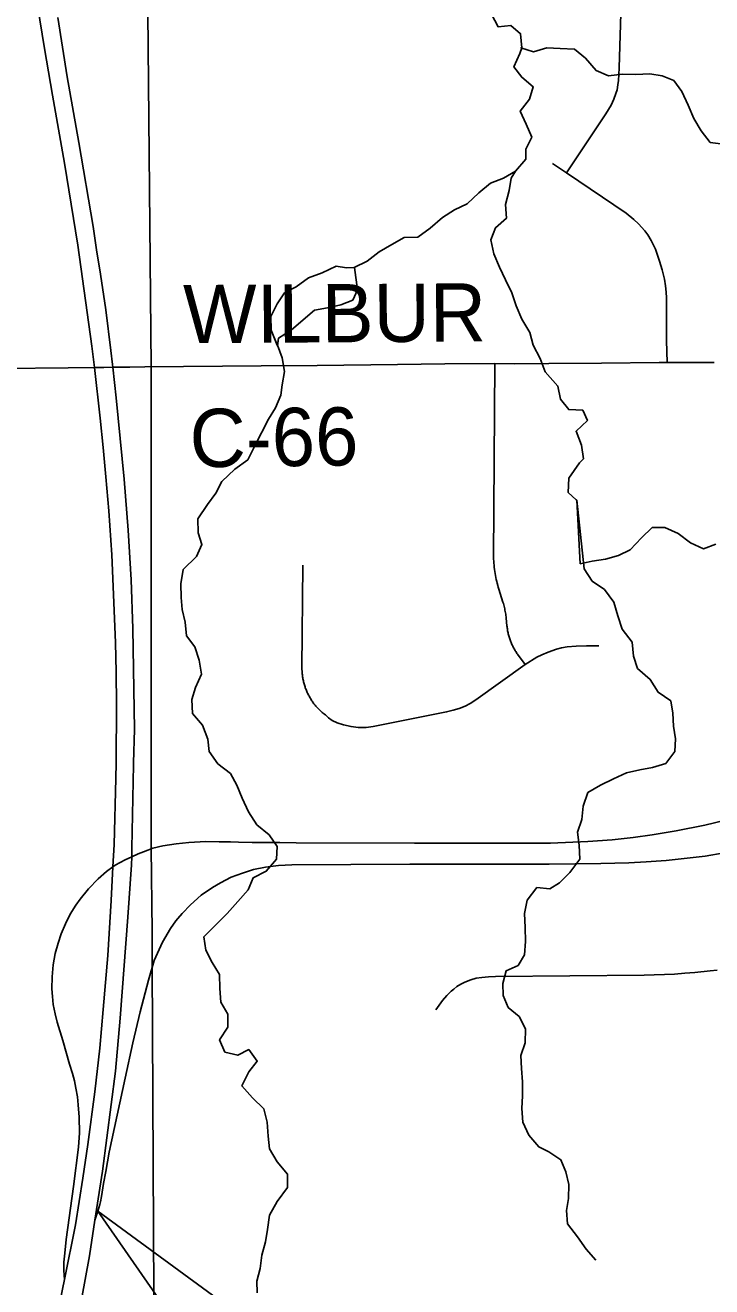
# Model space of a CAD drawing. Extents: x 0 to 34, y 0 to 22.
# Drawn here: x 2.725 to 3.395, y 15.885 to 17.117 of the extents above; entities that cross this region are included whole.
import ezdxf

# ---------------------------------------------------------------- set-up
doc = ezdxf.new("R2010")
doc.units = 0
for name, color, linetype in [('GM_X_Corporation', 7, 'Continuous'), ('GM_X_County_Road', 7, 'Continuous'), ('GM_X_County_Road_Text', 7, 'Continuous'), ('GM_X_Interstate_Route', 7, 'Continuous'), ('GM_X_Minor_Lake', 7, 'Continuous'), ('GM_X_Minor_River', 7, 'Continuous'), ('GM_X_Township_Road', 7, 'Continuous'), ('SH_Text', 7, 'Continuous')]:
    doc.layers.add(name, color=color, linetype=linetype)

msp = doc.modelspace()

# ---------------------------------------------------------------- linework, layer by layer
at = {"layer": 'GM_X_Corporation'}
msp.add_lwpolyline([(2.1, 19.0167), (2.1, 14.5179), (2.2213, 14.5194), (2.2958, 14.5199), (2.3573, 14.5203), (2.3767, 14.5206), (2.4262, 14.5205), (2.6122, 14.5212), (2.8483, 14.5213), (2.8655, 14.5214), (2.8502, 15.8768), (2.8488, 16.2), (2.8487, 16.2273), (2.8487, 16.232), (2.8477, 16.3135), (2.8476, 16.3157), (2.8477, 16.7834), (2.837, 17.9259), (2.8293, 18.7154), (2.8247, 19.0323), (2.4392, 19.024), (2.4288, 19.0238), (2.421, 19.0236)], close=True, dxfattribs=at)
msp.add_lwpolyline([(3.735, 14.5275), (3.3839, 14.5264), (3.3511, 14.525), (2.8655, 14.5214), (2.8502, 15.8768), (2.8488, 16.2), (2.8487, 16.2273), (2.8487, 16.232), (2.8477, 16.3135), (2.8476, 16.3157), (2.8477, 16.7834), (2.837, 17.9259), (2.8293, 18.7154)], dxfattribs=at)
at = {"layer": 'GM_X_County_Road'}
for points in [[(2.8415, 16.7834), (2.9551, 16.7841), (3.0098, 16.7846), (3.0879, 16.7857), (3.1342, 16.7862), (3.1831, 16.7864), (3.2019, 16.7863), (3.2356, 16.7864), (3.287, 16.7868), (3.3433, 16.7874), (3.351, 16.7874), (3.397, 16.7875)], [(2.6084, 16.7813), (2.6295, 16.781), (2.6551, 16.7811), (2.7026, 16.7818), (2.7666, 16.7822), (2.7924, 16.7825), (2.8017, 16.7826), (2.8104, 16.7828), (2.827, 16.7831), (2.8415, 16.7834)]]:
    msp.add_lwpolyline(points, dxfattribs=at)
at = {"layer": 'GM_X_Interstate_Route'}
msp.add_line((2.8403, 16.3099), (2.8446, 16.3115), dxfattribs=at)
for points in [[(2.8132, 16.3815), (2.8136, 16.3967), (2.814, 16.4537), (2.8136, 16.4853), (2.8129, 16.5142), (2.8093, 16.5997), (2.8065, 16.6426), (2.8036, 16.676), (2.8008, 16.7045), (2.798, 16.7331), (2.7924, 16.7825), (2.7899, 16.8036), (2.7762, 16.9019), (2.7631, 16.9822), (2.7516, 17.0485), (2.7437, 17.0939), (2.732, 17.1664)], [(2.8306, 16.3967), (2.8313, 16.4294), (2.8297, 16.528), (2.8281, 16.5753), (2.8252, 16.6239), (2.8213, 16.6735), (2.8137, 16.7531), (2.8104, 16.7828), (2.8101, 16.7857), (2.8085, 16.7991), (2.8036, 16.8389), (2.7984, 16.8736), (2.7945, 16.8976), (2.791, 16.9202), (2.777, 17.0024), (2.7659, 17.0664), (2.7566, 17.1244)], [(2.7769, 15.8595), (2.7791, 15.8703), (2.7796, 15.873), (2.7874, 15.9156), (2.7929, 15.9503), (2.8004, 15.9982), (2.8129, 16.0958), (2.8175, 16.1475), (2.8248, 16.2462), (2.8285, 16.2973), (2.8288, 16.3051), (2.829, 16.3133), (2.8306, 16.3947), (2.8306, 16.3967)], [(2.759, 15.872), (2.7631, 15.8925), (2.7738, 15.9459), (2.781, 15.9912), (2.786, 16.0242), (2.7927, 16.0757), (2.7975, 16.1183), (2.801, 16.156), (2.8053, 16.2087), (2.8087, 16.2624), (2.8104, 16.2954), (2.8115, 16.3171), (2.8132, 16.3815)], [(2.8446, 16.3115), (2.8493, 16.3133), (2.8592, 16.3158), (2.872, 16.3178), (2.8845, 16.3191), (2.901, 16.3199), (2.9142, 16.3197), (2.9251, 16.3195), (2.933, 16.3193), (2.9461, 16.3191), (2.9731, 16.3189), (2.9892, 16.3187), (3.1046, 16.3185), (3.2373, 16.3183), (3.2736, 16.3199), (3.2975, 16.3216), (3.3179, 16.3238), (3.3365, 16.3265), (3.36, 16.3304), (3.3878, 16.3358), (3.408, 16.3407)], [(2.7631, 15.8925), (2.7628, 15.8964), (2.7624, 15.9016), (2.7626, 15.9092), (2.7634, 15.9183), (2.7648, 15.9316), (2.7721, 15.9832), (2.7769, 16.0215), (2.7778, 16.0357), (2.7774, 16.0508), (2.7765, 16.0629), (2.7757, 16.0707), (2.7743, 16.0792), (2.7728, 16.0862), (2.771, 16.0934), (2.7682, 16.1026), (2.7614, 16.1258), (2.7561, 16.1437), (2.7541, 16.1517), (2.7522, 16.1608), (2.7515, 16.1686), (2.7508, 16.1763), (2.7512, 16.1878), (2.752, 16.1995), (2.7539, 16.2107), (2.757, 16.2208), (2.76, 16.23), (2.764, 16.2397), (2.7687, 16.2492), (2.7743, 16.2578), (2.7786, 16.2638), (2.7866, 16.2739), (2.7961, 16.2836), (2.8042, 16.2908), (2.8104, 16.2954), (2.8126, 16.297), (2.8223, 16.3021), (2.8288, 16.3051), (2.8351, 16.3079), (2.8403, 16.3099)], [(2.8737, 16.2447), (2.8779, 16.2497), (2.8861, 16.258), (2.8966, 16.2675), (2.9076, 16.275), (2.9153, 16.2797), (2.9258, 16.285), (2.9368, 16.2892), (2.9476, 16.2925), (2.9593, 16.295), (2.9721, 16.2965), (2.985, 16.2972), (3.1002, 16.298), (3.2361, 16.2977), (3.2864, 16.2984), (3.3136, 16.299), (3.3306, 16.3), (3.3501, 16.3015), (3.3881, 16.3057), (3.4068, 16.3089)], [(2.845, 16.1845), (2.8506, 16.2038), (2.8589, 16.2217), (2.8666, 16.235), (2.8719, 16.2425), (2.8737, 16.2447)], [(2.7929, 15.9503), (2.7956, 15.9593), (2.7965, 15.9624), (2.7975, 15.9657), (2.7982, 15.9683), (2.7992, 15.9736), (2.8013, 15.9861), (2.8034, 15.9977), (2.8069, 16.0167), (2.8225, 16.0891), (2.8299, 16.1236), (2.8371, 16.1538), (2.845, 16.1845)]]:
    msp.add_lwpolyline(points, dxfattribs=at)
at = {"layer": 'GM_X_Minor_Lake'}
for points in [[(3.046, 16.8802), (3.0382, 16.88), (3.0283, 16.8814), (3.0144, 16.8751), (3.0013, 16.8703), (2.9893, 16.8613), (2.9777, 16.8554), (2.9707, 16.8447), (2.9645, 16.8324), (2.9647, 16.8192), (2.9709, 16.8037)], [(3.0457, 16.8802), (3.0382, 16.88), (3.0283, 16.8814), (3.0144, 16.8751), (3.0013, 16.8703), (2.9893, 16.8613), (2.9777, 16.8554), (2.9707, 16.8447), (2.9645, 16.8324), (2.9647, 16.8192), (2.9706, 16.8044)], [(2.9709, 16.8037), (2.972, 16.8113), (2.9844, 16.8191), (2.9959, 16.8292), (3.0071, 16.8385), (3.0199, 16.841), (3.0328, 16.8439), (3.0444, 16.8483), (3.0491, 16.8586), (3.046, 16.8802)], [(2.971, 16.8045), (2.972, 16.8113), (2.9844, 16.8191), (2.9959, 16.8292), (3.0071, 16.8385), (3.0199, 16.841), (3.0328, 16.8439), (3.0444, 16.8483), (3.0491, 16.8586), (3.046, 16.8802)]]:
    msp.add_lwpolyline(points, dxfattribs=at)
at = {"layer": 'GM_X_Minor_River'}
for points in [[(3.1798, 17.1276), (3.1861, 17.1152), (3.1986, 17.1166), (3.2082, 17.1084), (3.2095, 17.0948)], [(3.2095, 17.0948), (3.2074, 17.089), (3.2015, 17.076), (3.2093, 17.0659), (3.2204, 17.0566), (3.2168, 17.0444), (3.2076, 17.0329), (3.2135, 17.0201), (3.219, 17.0073), (3.2132, 16.9958), (3.2133, 16.9859), (3.2033, 16.9744), (3.1913, 16.9673), (3.1789, 16.9626), (3.1674, 16.9532), (3.1559, 16.9424), (3.1435, 16.9365), (3.1319, 16.9291), (3.12, 16.9186), (3.108, 16.9097), (3.0944, 16.9095), (3.0824, 16.9028), (3.0701, 16.8954), (3.0585, 16.8864), (3.0457, 16.8802)], [(3.2095, 17.0948), (3.2084, 17.0947), (3.2206, 17.0908), (3.2337, 17.0948), (3.2466, 17.0939), (3.2606, 17.0934), (3.2714, 17.0845), (3.2818, 17.0725), (3.294, 17.0674), (3.3076, 17.0688), (3.3204, 17.0686), (3.3341, 17.0692), (3.3462, 17.0672), (3.3576, 17.0628), (3.3654, 17.052), (3.3717, 17.0388), (3.3772, 17.0256), (3.3842, 17.0136), (3.3931, 17.0024), (3.406, 17.0007)], [(3.2033, 16.9744), (3.1989, 16.9675), (3.1969, 16.9553), (3.1933, 16.9419), (3.1943, 16.9283), (3.1835, 16.919), (3.1792, 16.9072), (3.1821, 16.8935), (3.1876, 16.8807), (3.1935, 16.8683), (3.1997, 16.8555), (3.2038, 16.8427), (3.2093, 16.8299), (3.2171, 16.8168), (3.2203, 16.8043), (3.2273, 16.7915), (3.2321, 16.7783), (3.2445, 16.7645), (3.247, 16.7516), (3.2551, 16.7415), (3.2687, 16.741), (3.2734, 16.7308), (3.2623, 16.7204), (3.2674, 16.7068), (3.2695, 16.6936), (3.2655, 16.6897), (3.2551, 16.6747), (3.2546, 16.6607), (3.2623, 16.6536), (3.2631, 16.6533)], [(2.9071, 16.2019), (2.9009, 16.2139), (2.8991, 16.2268), (2.9106, 16.2384), (2.9218, 16.2496), (2.9322, 16.2615), (2.9422, 16.2727), (2.9473, 16.2846), (2.96, 16.2909), (2.97, 16.3028), (2.9706, 16.315), (2.9628, 16.3266), (2.9509, 16.3363), (2.9427, 16.349), (2.9365, 16.3622), (2.9313, 16.375), (2.9251, 16.3863), (2.9128, 16.3959), (2.9043, 16.4079), (2.9029, 16.42), (2.8977, 16.4336), (2.8881, 16.4448), (2.8875, 16.4585), (2.891, 16.4703), (2.8969, 16.4833), (2.8944, 16.4969), (2.8903, 16.5101), (2.8822, 16.5206), (2.8808, 16.5342), (2.878, 16.5463), (2.877, 16.5581), (2.8768, 16.5714), (2.8788, 16.5854), (2.8918, 16.5982), (2.8973, 16.61), (2.8937, 16.6214), (2.8931, 16.635), (2.9027, 16.6488), (2.9108, 16.66), (2.9166, 16.6715), (2.9293, 16.6835), (2.942, 16.6924), (2.9489, 16.7062), (2.9621, 16.7322), (2.9691, 16.7433), (2.9742, 16.7556), (2.9755, 16.7658), (2.9779, 16.7788), (2.9754, 16.792), (2.971, 16.8045)], [(3.2631, 16.6533), (3.2703, 16.5862), (3.2781, 16.5742), (3.2899, 16.5661), (3.2992, 16.5537), (3.3029, 16.5401), (3.3073, 16.5273), (3.317, 16.5146), (3.3183, 16.5009), (3.3223, 16.4889), (3.3346, 16.4781), (3.3424, 16.4657), (3.3547, 16.4572), (3.3568, 16.4451), (3.3574, 16.4325), (3.3591, 16.4201), (3.3585, 16.4079), (3.3497, 16.396), (3.3369, 16.3923), (3.3244, 16.3899), (3.3113, 16.387), (3.2989, 16.3811), (3.2861, 16.3751), (3.2738, 16.3677), (3.2691, 16.3544), (3.2678, 16.3414), (3.2635, 16.3292), (3.2652, 16.3163), (3.2658, 16.3027), (3.2562, 16.2896), (3.2462, 16.2796), (3.2365, 16.2737), (3.224, 16.275), (3.2147, 16.2627), (3.2119, 16.2498), (3.2125, 16.2361), (3.2128, 16.2224), (3.2119, 16.2095), (3.2056, 16.1988), (3.194, 16.1937), (3.1908, 16.1815), (3.191, 16.1697), (3.1961, 16.158), (3.2069, 16.1491), (3.2128, 16.1371), (3.2126, 16.1234), (3.2083, 16.1112), (3.2089, 16.0983), (3.2099, 16.0854), (3.2101, 16.0718), (3.2092, 16.0592), (3.2102, 16.046), (3.2161, 16.0332), (3.2258, 16.0219), (3.2357, 16.0172), (3.2475, 16.0094), (3.2523, 15.9974), (3.2551, 15.9853), (3.255, 15.9716), (3.2529, 15.9598), (3.2539, 15.9469), (3.2636, 15.9342), (3.2721, 15.9222), (3.2814, 15.9113)], [(3.2631, 16.6533), (3.2664, 16.5911), (3.2781, 16.5936), (3.2909, 16.5957), (3.3037, 16.599), (3.315, 16.6045), (3.3261, 16.6164), (3.3365, 16.6265), (3.349, 16.6263), (3.362, 16.6205), (3.3739, 16.6116), (3.3865, 16.6057), (3.3985, 16.6101)], [(2.951, 15.8794), (2.9508, 15.8908), (2.954, 15.9033), (2.9556, 15.9163), (2.9592, 15.9292), (2.9613, 15.9414), (2.9633, 15.9551), (2.9706, 15.9685), (2.9806, 15.9824), (2.9807, 15.9953), (2.9707, 16.0072), (2.9633, 16.02), (2.9619, 16.0325), (2.9609, 16.0461), (2.9577, 16.059), (2.9465, 16.0698), (2.9361, 16.0814), (2.943, 16.0952), (2.9512, 16.1055), (2.943, 16.1168), (2.9322, 16.1113), (2.9196, 16.1145), (2.9145, 16.1265), (2.9226, 16.1388), (2.9224, 16.1513), (2.9157, 16.163), (2.9147, 16.1766), (2.9145, 16.1903), (2.9071, 16.2019)]]:
    msp.add_lwpolyline(points, dxfattribs=at)
at = {"layer": 'GM_X_Township_Road'}
for points in [[(3.253, 16.9727), (3.2912, 17.0303), (3.2965, 17.0387), (3.2992, 17.0446), (3.3012, 17.05), (3.3022, 17.0536), (3.3029, 17.0585), (3.3036, 17.0628), (3.3041, 17.0686), (3.3044, 17.0752), (3.3074, 17.1813), (3.3072, 17.1868), (3.3067, 17.1931), (3.3063, 17.1965), (3.3057, 17.1998), (3.3042, 17.2054), (3.3027, 17.2102), (3.2892, 17.247), (3.2793, 17.2719)], [(3.351, 16.7874), (3.3506, 16.8091), (3.3505, 16.8507), (3.3503, 16.8561), (3.3494, 16.8624), (3.3484, 16.8687), (3.3462, 16.8779), (3.3437, 16.8864), (3.3397, 16.898), (3.3355, 16.9066), (3.3322, 16.912), (3.3294, 16.9161), (3.3233, 16.9229), (3.3187, 16.9271), (3.3112, 16.9332), (3.253, 16.9727), (3.2394, 16.9818)], [(3.2126, 16.4927), (3.2051, 16.5028), (3.2046, 16.5036), (3.204, 16.5045), (3.2035, 16.5053), (3.2029, 16.5061), (3.2024, 16.507), (3.2019, 16.5079), (3.2014, 16.5087), (3.201, 16.5096), (3.2005, 16.5105), (3.2001, 16.5114), (3.1997, 16.5123), (3.1993, 16.5132), (3.1989, 16.5141), (3.1985, 16.515), (3.1982, 16.5159), (3.1978, 16.5169), (3.1975, 16.5178), (3.1972, 16.5188), (3.1969, 16.5197), (3.1966, 16.5207), (3.1964, 16.5216), (3.1961, 16.5226), (3.1959, 16.5235), (3.1957, 16.5245), (3.1955, 16.5255), (3.1953, 16.5265), (3.1952, 16.5275), (3.195, 16.5284), (3.1949, 16.5294), (3.1948, 16.5304), (3.1941, 16.538), (3.1939, 16.5393), (3.1938, 16.5406), (3.1936, 16.542), (3.1934, 16.5433), (3.1931, 16.5446), (3.1929, 16.5459), (3.1926, 16.5472), (3.1923, 16.5485), (3.192, 16.5497), (3.1917, 16.551), (3.1913, 16.5523), (3.1909, 16.5536), (3.1869, 16.5662), (3.1863, 16.5681), (3.1858, 16.57), (3.1853, 16.572), (3.1848, 16.5739), (3.1843, 16.5758), (3.1839, 16.5778), (3.1835, 16.5797), (3.1832, 16.5817), (3.1829, 16.5836), (3.1826, 16.5856), (3.1824, 16.5876), (3.1822, 16.5896), (3.182, 16.5915), (3.1819, 16.5935), (3.1818, 16.5955), (3.1817, 16.5975), (3.1831, 16.7864)], [(2.9957, 16.5897), (2.9948, 16.4896), (2.995, 16.4846), (2.9951, 16.4836), (2.9952, 16.4826), (2.9953, 16.4816), (2.9955, 16.4807), (2.9956, 16.4797), (2.9958, 16.4787), (2.996, 16.4777), (2.9962, 16.4768), (2.9964, 16.4758), (2.9966, 16.4748), (2.9969, 16.4739), (2.9972, 16.4729), (2.9975, 16.472), (2.9978, 16.471), (2.9981, 16.4701), (2.9984, 16.4692), (2.9988, 16.4682), (2.9991, 16.4673), (2.9995, 16.4664), (2.9999, 16.4655), (3.0003, 16.4646), (3.0008, 16.4637), (3.0012, 16.4628), (3.0017, 16.462), (3.0022, 16.4611), (3.0027, 16.4602), (3.0032, 16.4594), (3.0037, 16.4585), (3.0042, 16.4577), (3.0048, 16.4569), (3.0053, 16.4561), (3.0059, 16.4553), (3.0065, 16.4545), (3.0071, 16.4537), (3.0077, 16.4529), (3.0084, 16.4522), (3.009, 16.4514), (3.0097, 16.4507), (3.0104, 16.45), (3.011, 16.4493), (3.0132, 16.4472), (3.0147, 16.4459), (3.0154, 16.4453), (3.0162, 16.4447), (3.0177, 16.4435), (3.0208, 16.4408), (3.0244, 16.4382), (3.0292, 16.4359), (3.0352, 16.4337), (3.0428, 16.4321), (3.0498, 16.4312), (3.0576, 16.4314), (3.0642, 16.4322), (3.0709, 16.4336), (3.1359, 16.4465), (3.1422, 16.4481), (3.1483, 16.4499), (3.1541, 16.452), (3.159, 16.4547), (3.1645, 16.4583), (3.2126, 16.4927), (3.224, 16.4999), (3.2288, 16.5023), (3.2351, 16.5049), (3.2432, 16.5077), (3.248, 16.5089), (3.2535, 16.5099), (3.2625, 16.5106), (3.2724, 16.5108), (3.2844, 16.5111)], [(3.1256, 16.1557), (3.1321, 16.1647), (3.1361, 16.1696), (3.1405, 16.1739), (3.1429, 16.1759), (3.146, 16.1783), (3.1499, 16.1807), (3.1536, 16.1826), (3.1596, 16.1848), (3.1648, 16.1865), (3.1703, 16.1873), (3.1767, 16.1879), (3.1838, 16.1882), (3.3287, 16.1895), (3.3386, 16.1897), (3.3485, 16.1901), (3.3584, 16.1906), (3.3683, 16.1913), (3.3782, 16.1921), (3.393, 16.1938), (3.4, 16.1945)]]:
    msp.add_lwpolyline(points, dxfattribs=at)
at = {"layer": 'SH_Text'}
msp.add_lwpolyline([(3.4887, 15.4514), (2.7956, 15.9593), (3.4887, 14.9614)], close=True, dxfattribs=at)

# ---------------------------------------------------------------- texts
at = {"layer": 'GM_X_County_Road_Text'}
for s, rotation, p in [('WILBUR', 0.3487, (2.8791, 16.8063)), ('C-66', 0.6858, (2.8855, 16.6852))]:
    msp.add_text(s, height=0.05682, rotation=rotation, dxfattribs=at).set_placement(p)

doc.saveas('drawing.dxf')
